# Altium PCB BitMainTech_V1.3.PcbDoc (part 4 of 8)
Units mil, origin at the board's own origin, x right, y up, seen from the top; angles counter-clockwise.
Board outline 9842.52 x 6082.68 mil, 4 copper layers (Top Layer, Mid-Layer 1, Mid-Layer 2, Bottom Layer); 987 components, 282 nets, 3694 pads, 3174 vias.
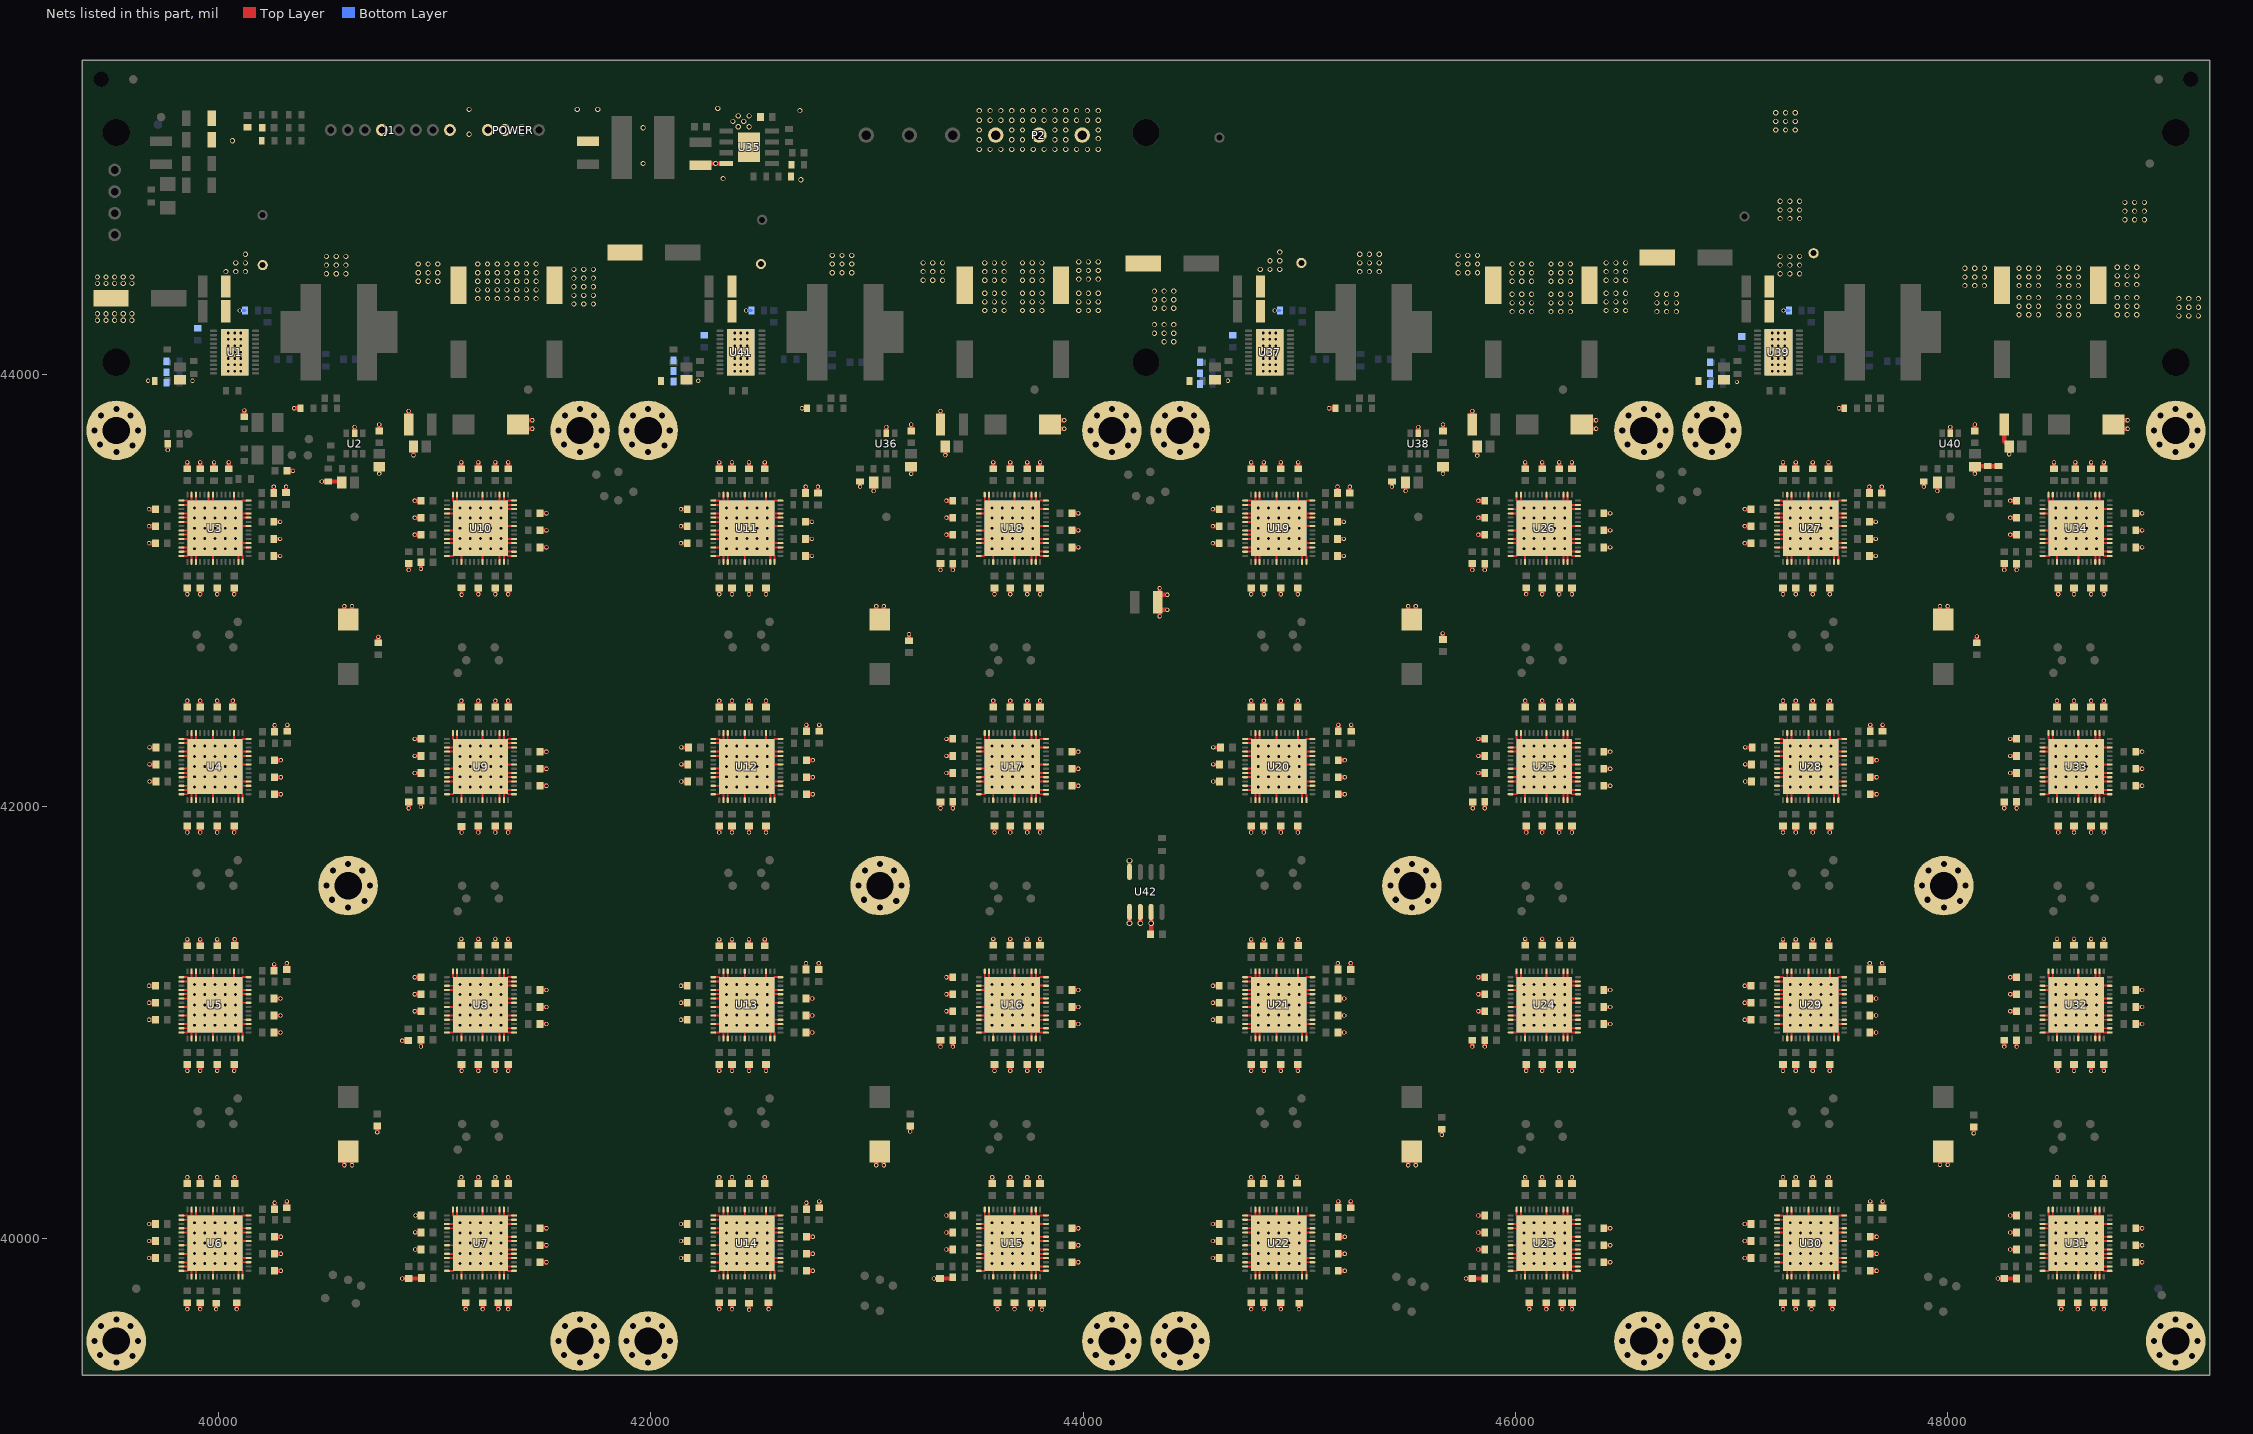
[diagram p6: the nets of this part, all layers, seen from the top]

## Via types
v1: diameter 19, hole 12, Top Layer to Bottom Layer, 1347 vias
v2: diameter 25.98, hole 12.99, Top Layer to Bottom Layer, 800 vias
v3: diameter 24, hole 16, Top Layer to Bottom Layer, 778 vias
v4: diameter 50, hole 28, Top Layer to Bottom Layer, 160 vias
v5: diameter 19.68, hole 11.81, Top Layer to Bottom Layer, 84 vias
v6: diameter 26, hole 18, Top Layer to Bottom Layer, 5 vias

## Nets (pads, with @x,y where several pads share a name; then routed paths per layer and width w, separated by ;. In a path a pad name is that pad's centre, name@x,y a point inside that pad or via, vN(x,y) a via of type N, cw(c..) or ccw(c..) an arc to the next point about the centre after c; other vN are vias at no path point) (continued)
GND: C2.2 C3.2 C4.2 C5.2 C6.2 C7.2 C8.1 C9.1 C13.2 C14.1 C15.1 C16.1 C17.2 C18.2 C19.1 C20.1 C21.2 C22.1 C23.2 C24.1 C25.2 C26.1 C27.2 C28.1 C29.2 C30.2 C31.2 C32.1 C33.1 C34.1 C35.1 C36.1 C37.1 C38.1 C39.1 C40.1 C41.1 C42.1 C43.1 C44.1 C45.1 C46.1 C47.1 C48.1 C49.1 C50.1 C51.1 C52.1 C53.1 C54.1 C55.1 C56.1 C57.1 C58.1 C59.1 C60.1 C61.1 C62.1 C63.1 C64.1 C65.1 C66.1 C67.1 C68.1 C69.1 C70.1 C71.1 C72.1 C73.1 C74.1 C75.1 C76.1 C77.1 C78.1 C79.1 C80.1 C81.1 C82.1 C83.1 C84.1 C85.1 C86.1 C87.1 C88.2 C89.1 C90.2 C91.1 C92.2 C93.1 C94.2 C95.1 C96.1 C97.1 C98.1 C99.1 C100.1 C101.1 C102.1 C103.1 C104.1 C105.1 C106.1 C107.1 C108.1 C109.1 C110.1 C111.1 C112.1 C113.1 C114.1 C115.1 C116.1 C117.1 C118.1 C119.1 C120.1 C121.1 C122.1 C123.1 C124.1 C125.1 C126.1 C127.1 C128.1 C129.1 C130.1 C131.1 C132.1 C133.1 C134.1 C135.1 C136.1 C137.1 C138.1 C139.1 C140.1 C141.1 C142.1 C143.1 C144.1 C145.1 C146.1 C147.1 C148.1 C149.1 C150.1 C151.1 C152.2 C153.2 C154.1 C155.1 C156.2 C157.1 C158.2 C159.1 C160.2 C161.1 C162.2 C163.1 C164.1 C165.1 C166.1 C167.1 C168.1 C169.1 C170.1 C171.1 C172.1 C173.1 C174.1 C175.1 C176.1 C177.1 C178.1 C179.1 C180.1 C181.1 C182.1 C183.1 C184.1 C185.1 C186.1 C187.1 C188.1 C189.1 C190.1 C191.1 C192.1 C193.1 C194.1 C195.1 C196.1 C197.1 C198.1 C199.1 C200.1 C201.1 C202.1 C203.1 C204.1 C205.1 C206.1 C207.1 C208.1 C209.1 C210.1 C211.1 C212.1 C213.1 C214.1 C215.1 C216.1 C217.1 C218.1 C219.1 C220.2 C221.1 C222.2 C223.1 C224.2 C225.1 C226.2 C227.1 C228.1 C229.1 C230.1 C231.1 C232.1 C233.1 C234.1 C235.1 C236.1 C237.1 C238.1 C239.1 C240.1 C241.1 C242.1 C243.1 C244.1 C245.1 C246.1 C247.1 C248.1 C249.1 C250.1 C251.1 C252.1 C253.1 C254.1 C255.1 C256.1 C257.1 C258.1 C259.1 C260.1 C261.1 C262.1 C263.1 C264.1 C265.1 C266.1 C267.1 C268.1 C269.1 C270.1 C271.1 C272.1 C273.1 C274.1 C275.1 C276.1 C277.1 C278.1 C279.1 C280.1 C281.1 C282.1 C283.1 C284.2 C285.2 C286.1 C287.1 C288.2 C289.1 C290.2 C291.1 C292.2 C293.1 C294.2 C295.1 C296.1 C297.1 C298.1 C299.1 C300.1 C301.1 C302.1 C303.1 C304.1 C305.1 C306.1 C307.1 C308.1 C309.1 C310.1 C311.1 C312.1 C313.1 C314.1 C315.1 C316.1 C317.1 C318.1 C319.1 C320.1 C321.1 C322.1 C323.1 C324.1 C325.1 C326.1 C327.1 C328.1 C329.1 C330.1 C331.1 C332.1 C333.1 C334.1 C335.1 C336.1 C337.1 C338.1 C339.1 C340.1 C341.1 C342.1 C343.1 C344.1 C345.1 C346.1 C347.1 C348.1 C349.1 C350.1 C351.1 C352.2 C353.1 C354.2 C355.1 C356.2 C357.1 C358.2 C359.1 C360.1 C361.1 C362.1 C363.1 C364.1 C365.1 C366.1 C367.1 C368.1 C369.1 C370.1 C371.1 C372.1 C373.1 C374.1 C375.1 C376.1 C377.1 C378.1 C379.1 C380.1 C381.1 C382.1 C383.1 C384.1 C385.1 C386.1 C387.1 C388.1 C389.1 C390.1 C391.1 C392.1 C393.1 C394.1 C395.1 C396.1 C397.1 C398.1 C399.1 C400.1 C401.1 C402.1 C403.1 C404.1 C405.1 C406.1 C407.1 C408.1 C409.1 C410.1 C411.1 C412.1 C413.1 C414.1 C415.1 C416.2 C417.2 C418.1 C419.1 C420.2 C421.1 C422.2 C423.1 C424.2 C425.1 C426.2 C427.1 C428.1 C429.1 C430.1 C431.1 C432.1 C433.1 C434.1 C435.1 C436.1 C437.1 C438.1 C439.1 C440.1 C441.1 C442.1 C443.1 C444.1 C445.1 C446.1 C447.1 C448.1 C449.1 C450.1 C451.1 C452.1 C453.1 C454.1 C455.1 C456.1 C457.1 C458.1 C459.1 C460.1 C461.1 C462.1 C463.1 C464.1 C465.1 C466.1 C467.1 C468.1 C469.1 C470.1 C471.1 C472.1 C473.1 C474.1 C475.1 C476.1 C477.1 C478.1 C479.1 C480.1 C481.1 C482.1 C483.1 C484.2 C485.1 C486.2 C487.1 C488.2 C489.1 C490.2 C491.1 C492.1 C493.1 C494.1 C495.1 C496.1 C497.1 C498.1 C499.1 C500.1 C501.1 C502.1 C503.1 C504.1 C505.1 C506.1 C507.1 C508.1 C509.1 C510.1 C511.1 C512.1 C513.1 C514.1 C515.1 C516.1 C517.1 C518.1 C519.1 C520.1 C521.1 C522.1 C523.1 C524.1 C525.1 C526.1 C527.1 C528.1 C529.1 C530.1 C531.1 C532.1 C533.1 C534.1 C535.1 C536.1 C537.1 C538.1 C539.1 C540.1 C541.1 C542.1 C543.1 C544.1 C545.1 C546.1 C547.1 C548.1 C550.1 C552.2 C553.2 C554.2 C555.1 C556.1 C560.2 C561.1 C562.1 C563.1 C565.2 C566.2 C567.2 C568.2 C569.2 C570.2 C571.1 C572.1 C576.2 C577.1 C578.1 C579.1 C581.2 C582.2 C583.2 C584.2 C585.2 C586.2 C587.1 C588.1 C592.2 C593.1 C594.1 C595.1 C596.2 C597.2 C599.2 C600.2 C601.2 C602.1 C604.2 C605.2 C606.2 C607.2 C608.2 C609.2 FB35.2 FB36.2 J1.4 J1.8 M4.0 M5.0 M6.0 M7.0 M8.0 M9.0 M10.0 M11.0 M12.0 M13.0 M14.0 M15.0 M16.0 M17.0 M18.0 M19.0 M20.0 M21.0 M22.0 M23.0 P2.1 P2.2 P2.3 POWER.1 POWER.2 R7.2 R8.2 R9.2 R10.2 R11.2 R12.2 R14.1 R19.1 R20.1 R25.1 R28.2 R29.2 R30.2 R31.2 R32.2 R33.2 R35.1 R42.2 R43.2 R44.2 R45.2 R46.2 R47.2 R49.1 R56.2 R57.2 R58.2 R59.2 R60.2 R61.2 R63.1 R72.1 R73.1 TP3.1 TP166.1 TP170.1 TP174.1 U1.PG U2.2 U3.3 U3.8 U3.9 U3.12 U3.13 U3.15 U3.16 U3.18 U3.19 U3.20 U3.22 U3.23 U3.24 U3.26 U3.27 U3.28 U3.30 U3.31 U3.35 U3.41 U3.42 U3.45 U3.46 U3.50 U3.52 U3.53 U3.56 U3.57 U4.3 U4.8 U4.12 U4.13 U4.15 U4.16 U4.18 U4.19 U4.22 U4.23 U4.24 U4.26 U4.27 U4.28 U4.30 U4.31 U4.35 U4.41 U4.42 U4.45 U4.46 U4.50 U4.52 U4.53 U4.56 U4.57 U5.3 U5.8 U5.12 U5.13 U5.15 U5.16 U5.18 U5.19 U5.20 U5.22 U5.24 U5.26 U5.27 U5.28 U5.30 U5.31 U5.35 U5.41 U5.42 U5.45 U5.46 U5.50 U5.52 U5.53 U5.56 U5.57 U6.3 U6.8 U6.12 U6.13 U6.15 U6.16 U6.18 U6.19 U6.22 U6.24 U6.26 U6.27 U6.28 U6.30 U6.31 U6.35 U6.41 U6.42 U6.45 U6.46 U6.50 U6.52 U6.53 U6.56 U6.57 U7.3 U7.8 U7.12 U7.13 U7.15 U7.16 U7.18 U7.19 U7.20 U7.22 U7.23 U7.26 U7.27 U7.28 U7.30 U7.31 U7.35 U7.41 U7.42 U7.45 U7.46 U7.50 U7.52 U7.53 U7.56 U7.57 U8.3 U8.8 U8.12 U8.13 U8.15 U8.16 U8.18 U8.19 U8.22 U8.23 U8.26 U8.27 U8.28 U8.30 U8.31 U8.35 U8.41 U8.42 U8.45 U8.46 U8.50 U8.52 U8.53 U8.56 U8.57 U9.3 U9.8 U9.12 U9.13 U9.15 U9.16 U9.18 U9.19 U9.20 U9.22 U9.26 U9.27 U9.28 U9.30 U9.31 U9.35 U9.41 U9.42 U9.45 U9.46 U9.50 U9.52 U9.53 U9.56 U9.57 U10.3 U10.8 U10.12 U10.13 U10.15 U10.16 U10.18 U10.19 U10.22 U10.26 U10.27 U10.28 U10.30 U10.31 U10.35 U10.41 U10.42 U10.45 U10.46 U10.50 U10.52 U10.53 U10.56 U10.57 U11.3 U11.8 U11.12 U11.13 U11.15 U11.16 U11.18 U11.19 U11.20 U11.22 U11.23 U11.24 U11.26 U11.28 U11.30 U11.31 U11.35 U11.41 U11.42 U11.45 U11.46 U11.50 U11.52 U11.53 U11.56 U11.57 U12.3 U12.8 U12.12 U12.13 U12.15 U12.16 U12.18 U12.19 U12.22 U12.23 U12.24 U12.26 U12.28 U12.30 U12.31 U12.35 U12.41 U12.42 U12.45 U12.46 U12.50 U12.52 U12.53 U12.56 U12.57 U13.3 U13.8 U13.12 U13.13 U13.15 U13.16 U13.18 U13.19 U13.20 U13.22 U13.24 U13.26 U13.28 U13.30 U13.31 U13.35 U13.41 U13.42 U13.45 U13.46 U13.50 U13.52 U13.53 U13.56 U13.57 U14.3 U14.8 U14.12 U14.13 U14.15 U14.16 U14.18 U14.19 U14.22 U14.24 U14.26 U14.28 U14.30 U14.31 U14.35 U14.41 U14.42 U14.45 U14.46 U14.50 U14.52 U14.53 U14.56 U14.57 U15.3 U15.8 U15.12 U15.13 U15.15 U15.16 U15.18 U15.19 U15.20 U15.22 U15.23 U15.26 U15.28 U15.30 U15.31 U15.35 U15.41 U15.42 U15.45 U15.46 U15.50 U15.52 U15.53 U15.56 U15.57 U16.3 U16.8 U16.12 U16.13 U16.15 U16.16 U16.18 U16.19 U16.22 U16.23 U16.26 U16.28 U16.30 U16.31 U16.35 U16.41 U16.42 U16.45 U16.46 U16.50 U16.52 U16.53 U16.56 U16.57 U17.3 U17.8 U17.12 U17.13 U17.15 U17.16 U17.18 U17.19 U17.20 U17.22 U17.26 U17.28 U17.30 U17.31 U17.35 U17.41 U17.42 U17.45 U17.46 U17.50 U17.52 U17.53 U17.56 U17.57 U18.3 U18.8 U18.12 U18.13 U18.15 U18.16 U18.18 U18.19 U18.22 U18.26 U18.28 U18.30 U18.31 U18.35 U18.41 U18.42 U18.45 U18.46 U18.50 U18.52 U18.53 U18.56 U18.57 U19.3 U19.8 U19.12 U19.13 U19.15 U19.16 U19.18 U19.19 U19.20 U19.22 U19.23 U19.24 U19.26 U19.27 U19.30 U19.31 U19.35 U19.41 U19.42 U19.45 U19.46 U19.50 U19.52 U19.53 U19.56 U19.57 U20.3 U20.8 U20.12 U20.13 U20.15 U20.16 U20.18 U20.19 U20.22 U20.23 U20.24 U20.26 U20.27 U20.30 U20.31 U20.35 U20.41 U20.42 U20.45 U20.46 U20.50 U20.52 U20.53 U20.56 U20.57 U21.3 U21.8 U21.12 U21.13 U21.15 U21.16 U21.18 U21.19 U21.20 U21.22 U21.24 U21.26 U21.27 U21.30 U21.31 U21.35 U21.41 U21.42 U21.45 U21.46 U21.50 U21.52 U21.53 U21.56 U21.57 U22.3 U22.8 U22.12 U22.13 U22.15 U22.16 U22.18 U22.19 U22.22 U22.24 U22.26 U22.27 U22.30 U22.31 U22.35 U22.41 U22.42 U22.45 U22.46 U22.50 U22.52 U22.53 U22.56 U22.57 U23.3 U23.8 U23.12 U23.13 U23.15 U23.16 U23.18 U23.19 U23.20 U23.22 U23.23 U23.26 U23.27 U23.30 U23.31 U23.35 U23.41 U23.42 U23.45 U23.46 U23.50 U23.52 U23.53 U23.56 U23.57 U24.3 U24.8 U24.12 U24.13 U24.15 U24.16 U24.18 U24.19 U24.22 U24.23 U24.26 U24.27 U24.30 U24.31 U24.35 U24.41 U24.42 U24.45 U24.46 U24.50 U24.52 U24.53 U24.56 U24.57 U25.3 U25.8 U25.12 U25.13 U25.15 U25.16 U25.18 U25.19 U25.20 U25.22 U25.26 U25.27 U25.30 U25.31 U25.35 U25.41 U25.42 U25.45 U25.46 U25.50 U25.52 U25.53 U25.56 U25.57 U26.3 U26.8 U26.12 U26.13 U26.15 U26.16 U26.18 U26.19 U26.22 U26.26 U26.27 U26.30 U26.31 U26.35 U26.41 U26.42 U26.45 U26.46 U26.50 U26.52 U26.53 U26.56 U26.57 U27.3 U27.8 U27.12 U27.13 U27.15 U27.16 U27.18 U27.19 U27.20 U27.22 U27.23 U27.24 U27.26 U27.30 U27.31 U27.35 U27.41 U27.42 U27.45 U27.46 U27.50 U27.52 U27.53 U27.56 U27.57 U28.3 U28.8 U28.12 U28.13 U28.15 U28.16 U28.18 U28.19 U28.22 U28.23 U28.24 U28.26 U28.30 U28.31 U28.35 U28.41 U28.42 U28.45 U28.46 U28.50 U28.52 U28.53 U28.56 U28.57 U29.3 U29.8 U29.12 U29.13 U29.15 U29.16 U29.18 U29.19 U29.20 U29.22 U29.24 U29.26 U29.30 U29.31 U29.35 U29.41 U29.42 U29.45 U29.46 U29.50 U29.52 U29.53 U29.56 U29.57 U30.3 U30.8 U30.12 U30.13 U30.15 U30.16 U30.18 U30.19 U30.22 U30.24 U30.26 U30.30 U30.31 U30.35 U30.41 U30.42 U30.45 U30.46 U30.50 U30.52 U30.53 U30.56 U30.57 U31.3 U31.8 U31.12 U31.13 U31.15 U31.16 U31.18 U31.19 U31.20 U31.22 U31.23 U31.26 U31.30 U31.31 U31.35 U31.41 U31.42 U31.45 U31.46 U31.50 U31.52 U31.53 U31.56 U31.57 U32.3 U32.8 U32.12 U32.13 U32.15 U32.16 U32.18 U32.19 U32.22 U32.23 U32.26 U32.30 U32.31 U32.35 U32.41 U32.42 U32.45 U32.46 U32.50 U32.52 U32.53 U32.56 U32.57 U33.3 U33.8 U33.12 U33.13 U33.15 U33.16 U33.18 U33.19 U33.20 U33.22 U33.26 U33.30 U33.31 U33.35 U33.41 U33.42 U33.45 U33.46 U33.50 U33.52 U33.53 U33.56 U33.57 U34.3 U34.8 U34.12 U34.13 U34.15 U34.16 U34.18 U34.19 U34.22 U34.26 U34.30 U34.31 U34.35 U34.41 U34.42 U34.45 U34.46 U34.50 U34.52 U34.53 U34.56 U34.57 U35.0 U35.4 U36.2 U37.PG U38.2 U39.PG U40.2 U41.PG U42.4 U42.5 U42.6 U42.7 | length 55928
  Top Layer w8: v2(39984.25,39980.32) v2(40031.5,39933.07) 40072.83,39891.73 U6.45@40139.76,39891.73 ; U5.57@40072.83,40994.09 U5.45@40139.76,40994.09 ; U4.57@40072.83,42096.46 U4.45@40139.76,42096.46 ; U3.57@40072.83,43198.82 U3.45@40139.76,43198.82 ; U7.45@41057.09,40068.9 U7.57@41124.02,40068.9 ; U8.45@41057.09,41171.26 U8.57@41124.02,41171.26 ; U9.45@41057.09,42273.62 U9.57@41124.02,42273.62 ; U10.45@41057.09,43375.98 U10.57@41124.02,43375.98 ; U14.57@42533.46,39891.73 U14.45@42600.39,39891.73 ; U13.57@42533.46,40994.09 U13.45@42600.39,40994.09 ; U12.57@42533.46,42096.46 U12.45@42600.39,42096.46 ; U11.57@42533.46,43198.82 U11.45@42600.39,43198.82 ; U15.45@43517.72,40068.9 U15.57@43584.65,40068.9 ; U16.45@43517.72,41171.26 U16.57@43584.65,41171.26 ; U17.45@43517.72,42273.62 U17.57@43584.65,42273.62 ; U18.45@43517.72,43375.98 U18.57@43584.65,43375.98 ; U22.57@44994.09,39891.73 U22.45@45061.02,39891.73 ; U21.57@44994.09,40994.09 U21.45@45061.02,40994.09 ; U20.57@44994.09,42096.46 U20.45@45061.02,42096.46 ; U19.57@44994.09,43198.82 U19.45@45061.02,43198.82 ; U23.45@45978.35,40068.9 U23.57@46045.28,40068.9 ; U24.45@45978.35,41171.26 U24.57@46045.28,41171.26 ; U25.45@45978.35,42273.62 U25.57@46045.28,42273.62 ; U26.45@45978.35,43375.98 U26.57@46045.28,43375.98 ; U30.57@47454.72,39891.73 U30.45@47521.65,39891.73 ; U29.57@47454.72,40994.09 U29.45@47521.65,40994.09 ; U28.57@47454.72,42096.46 U28.45@47521.65,42096.46 ; U27.57@47454.72,43198.82 U27.45@47521.65,43198.82 ; U31.45@48438.98,40068.9 U31.57@48505.91,40068.9 ; U32.45@48438.98,41171.26 U32.57@48505.91,41171.26 ; U33.45@48438.98,42273.62 U33.57@48505.91,42273.62 ; U34.45@48438.98,43375.98 U34.57@48505.91,43375.98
